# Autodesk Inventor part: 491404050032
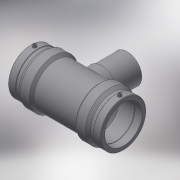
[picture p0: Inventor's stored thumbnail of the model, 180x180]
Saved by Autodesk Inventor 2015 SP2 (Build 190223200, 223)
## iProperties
Created: 2017-06
Part Number: 491404050032
Material: Generic
Description: PLASSON REDUCING TEE 50x32x50
Document SubType Name: Modeling
Designer: KIM
Mass: 236.237 g
Surface Area: 661.799 cm^2
Volume: 236.237 cm^3
Density: 1 g/cm^3
Appearance: Default
Author: KIM
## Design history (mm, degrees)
derived "491404.ipt"
feature "Solid1::491404.ipt"
tag "TaggingFeature1"
body "Solid1"
other parameters: "d0" = 139, "d2" = 68, "d3" = 48, "d4" = 27.8, "d5" = 61.2, "d6" = 47.5, "d8" = 168 deg, "d10" = 19.2, "d11" = 6.4, "d13" = 139, "d14" = 17.6296, "d17" = 45, "d19" = 3.52592, "d20" = 168 deg, "d22" = 63.24, "d23" = 68, "d25" = 135 deg, "d26" = 97.3, "d29" = 52, "d30" = 15, "d31" = 55.6, "d34" = 5 deg, "d35" = 15, "d39" = 5 deg, "d41" = 4, "d42" = 14, "d43" = 0, "d45" = 4, "d46" = 6, "d47" = 0, "d48" = -86, "d49" = 32, "d51" = 0, "d52" = 25.6, "d54" = 0, "d55" = 61.2, "d56" = 68, "d57" = 48.65, "d58" = 135 deg, "d59" = 48, "d60" = 48, "d61" = 135 deg, "d62" = 86, "d72" = 63.245, "d73" = 31.6225, "d74" = -86, "d75" = 33.6, "d77" = 0, "d78" = 25.6, "d80" = 0, "d81" = 32, "d82" = 52, "d83" = 0, "d84" = 3, "d85" = 0, "d86" = 16, "d87" = 61.9752, "d88" = 6.4, "d89" = 3, "d90" = 0, "L_" = 139, "L_1" = 48, "D_" = 68, "A_" = 52, "d_2" = 12, "H_" = 86, "d_1" = 32
